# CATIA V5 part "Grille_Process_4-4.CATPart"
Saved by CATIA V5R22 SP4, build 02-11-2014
Part number: Grille
Bounding box of the stored display mesh (mm): x -1100 to 0, y -500 to 500, z 0 to 558.819
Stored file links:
  C:\DATA\Car_ASSY\教育モデル\4_SUR\Grille_Process_4-4.CATPart
  C:\DATA\Car_ASSY\教育モデル\4_SUR\Grille_FIN.CATPart
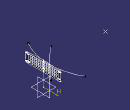
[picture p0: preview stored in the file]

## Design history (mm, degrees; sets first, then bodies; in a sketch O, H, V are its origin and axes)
Set1 "Boss_Danmen"
  Sketch1 on Plane1, origin (-185, 0, 0), H (0, 1, 0), V (0, 0, 1)
    circle A1 centre (-280, 370) radius 6
    circle A2 centre (-280, 260) radius 6
    circle A3 centre (280, 370) radius 6
    circle A4 centre (280, 260) radius 6
    circle A5 centre (-280, 370) radius 9
    point P1 (-280, 370)
    circle A6 centre (-280, 260) radius 9
    point P2 (-280, 260)
    circle A7 centre (280, 260) radius 9
    point P3 (280, 260)
    circle A8 centre (280, 370) radius 9
    point P4 (280, 370)
    radius A5 = 9
    radius A6 = 9
    radius A7 = 9
    radius A8 = 9
    distance P4 V = 280
    distance H P4 = 370
    radius A3 = 6
    distance P3 P4 = 110
    distance V P3 = 280
    radius A4 = 6
    radius A2 = 6
    radius A1 = 6
    distance P1 V = 280
    distance P2 V = 280
    distance H P2 = 260
    distance P2 P1 = 110
    concentricity: P1 A1, P2 A2, P3 A4, P4 A3
  Plane1: type Offset, RefPlane yz-plane, Offset -185
Set2 "Front"
  Point1: (-1100, 0, 300)
  Circle1: type CtrRad, Start -30, End 30, Radius 1000, FirstDirection (1, 0, 0), Center Point1, Support xy-plane
  Circle2: type CtrRad, Start 165, End 195, Radius 1000, FirstDirection (-1, 0, 0), Center Point1, Support zx-plane
Body1 (main body)
Body2
  Sketch2 on yz-plane, origin (0, 0, 0), H (0, 1, 0), V (0, 0, 1)
    point P1 (0.0002, 410)
    construction line L1 (0.0002, 410) -> (310, 410)
    point P2 (310, 410)
    line L2 (310, 372.6426) -> (310, 250)
    point P3 (310, 230)
    line L3 (290, 230) -> (0, 230)
    point P4 (0, 230)
    circle A1 centre (280, 370) radius 8
    circle A2 centre (280, 260) radius 8
    spline S1 through (0.0002, 410) (184.2802, 403.8794) (310, 390)
    arc A3 centre (290, 250) radius 20 from (290, 230) to (310, 250) ccw
    point P5 (290, 230)
    point P6 (310, 250)
    arc A4 centre (290, 372.6426) radius 20 from (292.7155, 392.4574) to (310, 372.6426) cw
    point P8 (292.7155, 392.4574)
    point P9 (310, 372.6426)
    offsetcurve C1
    point P11 (0.0002, 390)
    point P12 (290.0001, 372.6425)
    construction line L4 (0.0002, 410) -> (0.0002, 390)
    point P13 (0.0002, 410)
    construction line L5 through (0.0002, 410) direction (-1, 0)
    construction line L6 (292.7155, 392.4574) -> (290.0001, 372.6425)
    construction line L7 through (292.7155, 392.4574) direction (0.9907, -0.1358)
    line L8 (260, 376.4843) -> (260, 255)
    point P14 (257.373, 372.6426)
    point P15 (257.373, 250)
    construction line L9 (310, 372.6426) -> (257.373, 372.6426)
    construction line L10 (310, 250) -> (257.373, 250)
    line L11 (255, 250) -> (0, 250)
    point P16 (290, 250)
    point P17 (0, 250)
    construction line L12 (290, 230) -> (290, 250)
    construction line L13 (0, 230) -> (0, 250)
    point P18 (260, 376.4843)
    point P19 (260, 250)
    line L14 (272, 370) -> (260, 370)
    point P20 (272, 370)
    point P21 (260, 370)
    line L15 (288, 370) -> (310, 370)
    point P22 (288, 370)
    point P23 (310, 370)
    line L16 (288, 260) -> (310, 260)
    point P24 (288, 260)
    point P25 (310, 260)
    line L17 (272, 260) -> (260, 260)
    point P26 (272, 260)
    point P27 (260, 260)
    line L18 (260, 275) -> (0, 275)
    point P28 (260, 275)
    point P29 (0, 275)
    construction line L19 (260, 250) -> (260, 275)
    construction line L20 (0, 250) -> (0, 275)
    line L21 (260, 300) -> (0, 300)
    point P30 (260, 300)
    point P31 (0, 300)
    construction line L22 (260, 275) -> (260, 300)
    construction line L23 (0, 275) -> (0, 300)
    line L24 (260, 325) -> (0, 325)
    point P32 (260, 325)
    point P33 (0, 325)
    construction line L25 (260, 300) -> (260, 325)
    construction line L26 (0, 300) -> (0, 325)
    line L27 (260, 350) -> (0, 350)
    point P34 (260, 350)
    point P35 (0, 350)
    construction line L28 (260, 325) -> (260, 350)
    construction line L29 (0, 325) -> (0, 350)
    line L30 (260, 375) -> (0, 375)
    point P36 (260, 375)
    point P37 (0, 375)
    construction line L31 (260, 350) -> (260, 375)
    construction line L32 (0, 350) -> (0, 375)
    arc A5 centre (255, 255) radius 5 from (260, 255) to (255, 250) cw
    point P38 (260, 255)
    point P39 (255, 250)
    line L33 (17.5, 250) -> (17.5, 389.9532)
    point P41 (17.5, 250)
    point P42 (17.5, 389.9532)
    line L34 (52.5, 250) -> (52.5, 389.5709)
    point P43 (52.5, 250)
    point P44 (52.5, 389.5709)
    line L35 (87.5, 250) -> (87.5, 388.769)
    point P45 (87.5, 250)
    point P46 (87.5, 388.769)
    line L36 (122.5, 250) -> (122.5, 387.4859)
    point P47 (122.5, 250)
    point P48 (122.5, 387.4859)
    line L37 (157.5, 250) -> (157.5, 385.6484)
    point P49 (157.5, 250)
    point P50 (157.5, 385.6484)
    line L38 (192.5, 250) -> (192.5, 383.1854)
    point P51 (192.5, 250)
    point P52 (192.5, 383.1854)
    line L39 (227.5, 250) -> (227.5, 380.0419)
    point P53 (227.5, 250)
    point P54 (227.5, 380.0419)
    point P55 (-0.0002, 410)
    point P56 (-310, 410)
    construction line L40 (-0.0002, 410) -> (-310, 410)
    point P57 (-310, 230)
    point P58 (0, 230)
    point P59 (-290, 230)
    point P60 (-310, 250)
    point P62 (-292.7155, 392.4574)
    point P63 (-310, 372.6426)
    point P65 (-0.0002, 390)
    point P66 (-290.0001, 372.6425)
    point P67 (-257.373, 372.6426)
    point P68 (-257.373, 250)
    point P69 (-290, 250)
    point P70 (0, 250)
    point P71 (-260, 376.4843)
    point P72 (-260, 250)
    point P73 (-272, 370)
    point P74 (-260, 370)
    point P75 (-288, 370)
    point P76 (-310, 370)
    point P77 (-288, 260)
    point P78 (-310, 260)
    point P79 (-272, 260)
    point P80 (-260, 260)
    point P81 (-260, 275)
    point P82 (0, 275)
    point P83 (-260, 300)
    point P84 (0, 300)
    point P85 (-260, 325)
    point P86 (0, 325)
    point P87 (-260, 350)
    point P88 (0, 350)
    point P89 (-260, 375)
    point P90 (0, 375)
    point P91 (-260, 255)
    point P92 (-255, 250)
    point P94 (-17.5, 250)
    point P95 (-17.5, 389.9532)
    point P96 (-52.5, 250)
    point P97 (-52.5, 389.5709)
    point P98 (-87.5, 250)
    point P99 (-87.5, 388.769)
    point P100 (-122.5, 250)
    point P101 (-122.5, 387.4859)
    point P102 (-157.5, 250)
    point P103 (-157.5, 385.6484)
    point P104 (-192.5, 250)
    point P105 (-192.5, 383.1854)
    point P106 (-227.5, 250)
    point P107 (-227.5, 380.0419)
    line L41 (-310, 372.6426) -> (-310, 250)
    line L42 (-290, 230) -> (0, 230)
    circle A6 centre (-280, 370) radius 8
    circle A7 centre (-280, 260) radius 8
    spline S2 through (-0.0002, 410) (-184.2802, 403.8794) (-310, 390)
    arc A8 centre (-290, 250) radius 20 from (-290, 230) to (-310, 250) cw
    arc A9 centre (-290, 372.6426) radius 20 from (-292.7155, 392.4574) to (-310, 372.6426) ccw
    offsetcurve C2
    line L43 (-260, 376.4843) -> (-260, 255)
    line L44 (-255, 250) -> (0, 250)
    line L45 (-272, 370) -> (-260, 370)
    line L46 (-288, 370) -> (-310, 370)
    line L47 (-288, 260) -> (-310, 260)
    line L48 (-272, 260) -> (-260, 260)
    line L49 (-260, 275) -> (0, 275)
    line L50 (-260, 300) -> (0, 300)
    line L51 (-260, 325) -> (0, 325)
    line L52 (-260, 350) -> (0, 350)
    line L53 (-260, 375) -> (0, 375)
    arc A10 centre (-255, 255) radius 5 from (-260, 255) to (-255, 250) ccw
    line L54 (-17.5, 250) -> (-17.5, 389.9532)
    line L55 (-52.5, 250) -> (-52.5, 389.5709)
    line L56 (-87.5, 250) -> (-87.5, 388.769)
    line L57 (-122.5, 250) -> (-122.5, 387.4859)
    line L58 (-157.5, 250) -> (-157.5, 385.6484)
    line L59 (-192.5, 250) -> (-192.5, 383.1854)
    line L60 (-227.5, 250) -> (-227.5, 380.0419)
    point P108 (0.0002, 410)
    point P109 (310, 390)
    point P110 (184.2802, 403.8794)
    point P111 (-0.0002, 410)
    point P112 (-310, 390)
    point P113 (-184.2802, 403.8794)
    distance H L3 = 230
    distance L2 V = 310
    distance P109 L1 = 20
    distance P2 P3 = 180
    distance V P110 = 184.2802
    distance P110 P109 V = 13.8794
    distance P108 P4 = 180
    radius A3 = 20
    radius A4 = 20
    distance L2 L8 = 50
    distance L3 L11 = 20
    distance L16 L3 = 30
    distance L15 L16 = 110
    distance A1 L15 = 8
    distance A1 L15 = 8
    distance A1 L2 = 38
    distance A2 L16 = 8
    distance A2 L16 = 8
    distance L2 A2 = 38
    distance L11 L18 = 25
    distance L18 L21 = 25
    distance L21 L24 = 25
    distance L24 L27 = 25
    distance L27 L30 = 25
    radius A5 = 5
    distance V L33 = 17.5
    distance L33 L34 = 35
    distance L34 L35 = 35
    distance L35 L36 = 35
    distance L36 L37 = 35
    distance L37 L38 = 35
    distance L38 L39 = 35
    horizontal: L1 H, L3 H, L14 H, L15 H, L16 H, L17 H
    vertical: L2 V, L33 V, L34 V, L35 V, L36 V, L37 V, L38 V, L39 V
    coincidence: P4 V, P108 P1, P109 L2, P2 L2, L3 P3, L2 P3, P108 P13, P12 C1, P16 L11, P20 A1, P21 L8, P22 L14, P22 A1, P23 L2, P24 A2, P25 L2, P26 L16, P26 A2, P27 L8, L8 P19, L11 P19, P41 L11, P42 C1, P43 L11, P44 C1, P45 L11, P46 C1, P47 L11, P48 C1, P49 L11, P50 C1, P51 L11, P52 C1, P53 L11, P54 C1, P4 P58, P17 P70, P29 P82, P31 P84, P33 P86, P35 P88, P37 P90
    tangency: A3 L3, A3 L2, A4 S1, A4 L2, L5 S1, L7 S1, A5 L8, A5 L11
    perpendicularity: L4 L5, L6 L7, L9 L2, L9 L8, L10 L2, L10 L8, L12 L3, L12 L11, L13 L3, L13 L11, L19 L11, L19 L18, L20 L11, L20 L18, L22 L18, L22 L21, L23 L18, L23 L21, L25 L21, L25 L24, L26 L21, L26 L24, L28 L24, L28 L27, L29 L24, L29 L27, L31 L27, L31 L30, L32 L27, L32 L30
    symmetry: P1 P55 V, P2 P56 V, L1 L40 V, P3 P57 V, P4 P58 V, P5 P59 V, P6 P60 V, P8 P62 V, P9 P63 V, P11 P65 V, P12 P66 V, P14 P67 V, P15 P68 V, P16 P69 V, P17 P70 V, P18 P71 V, P19 P72 V, P20 P73 V, P21 P74 V, P22 P75 V, P23 P76 V, P24 P77 V, P25 P78 V, P26 P79 V, P27 P80 V, P28 P81 V, P29 P82 V, P30 P83 V, P31 P84 V, P32 P85 V, P33 P86 V, P34 P87 V, P35 P88 V, P36 P89 V, P37 P90 V, P38 P91 V, P39 P92 V, P41 P94 V, P42 P95 V, P43 P96 V, P44 P97 V, P45 P98 V, P46 P99 V, P47 P100 V, P48 P101 V, P49 P102 V, P50 P103 V, P51 P104 V, P52 P105 V, P53 P106 V, P54 P107 V, L2 L41 V, L3 L42 V, A1 A6 V, A2 A7 V, S1 S2 V, A3 A8 V, A4 A9 V, C1 C2 V, L8 L43 V, L11 L44 V, L14 L45 V, L15 L46 V, L16 L47 V, L17 L48 V, L18 L49 V, L21 L50 V, L24 L51 V, L27 L52 V, L30 L53 V, A5 A10 V, L33 L54 V, L34 L55 V, L35 L56 V, L36 L57 V, L37 L58 V, L38 L59 V, L39 L60 V, P108 P111 V, P109 P112 V, P110 P113 V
